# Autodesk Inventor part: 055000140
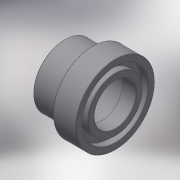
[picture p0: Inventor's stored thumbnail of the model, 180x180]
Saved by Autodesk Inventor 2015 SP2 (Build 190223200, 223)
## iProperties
Created: 2017-10
Part Number: 055000140
Material: Generic
Description: PLASSON FLANGE AD.+O-RING-CE 140
Document SubType Name: Modeling
Designer: KIM
Density: 1 g/cm^3
Appearance: Default
Author: KIM
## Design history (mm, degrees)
derived "055000.ipt"
feature "Solid1::055000.ipt"
tag "TaggingFeature1"
body "Solid1"
other parameters: "d0" = 88, "d1" = 163, "d3" = 126, "d4" = 18, "d5" = 76, "d6" = 188, "d8" = 5.4, "d11" = 1.4, "d12" = 5.4, "d15" = 9.3, "E_" = 163, "E_1" = 188, "l_" = 76, "B_" = 18, "H_" = 88, "d14" = 31
